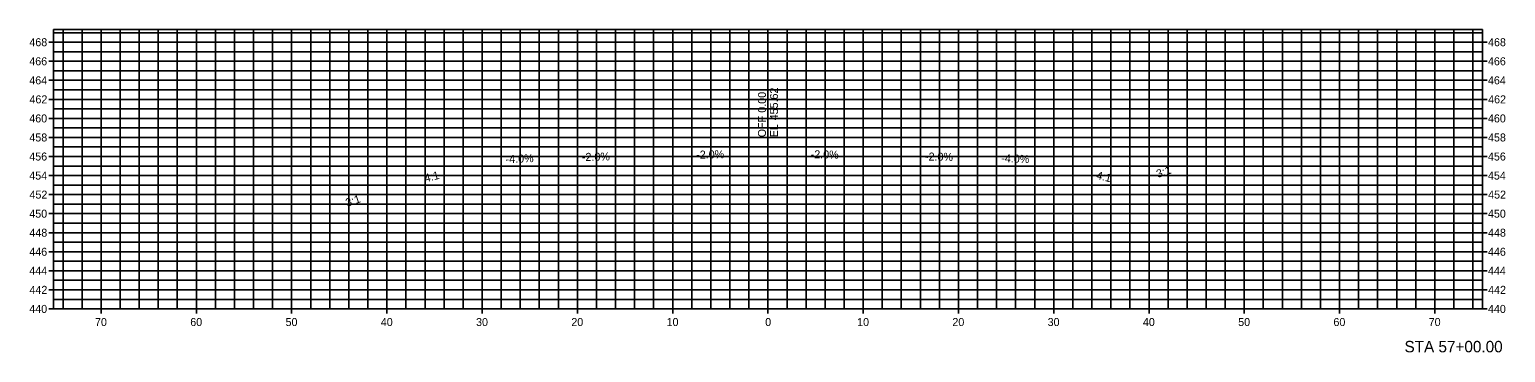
# Model space of a CAD drawing. Extents: x -78 to 77, y 435 to 469.
import ezdxf

# ---------------------------------------------------------------- set-up
doc = ezdxf.new("R2010")
doc.units = 0
for name, color, linetype in [('DSN_DRFT_XS Border Grid', 7, 'Continuous'), ('DSN_DRFT_XS Grid Annotations', 7, 'Continuous'), ('DSN_RDWY_XS Annotation', 7, 'Continuous')]:
    doc.layers.add(name, color=color, linetype=linetype)

msp = doc.modelspace()

# ---------------------------------------------------------------- linework, layer by layer
at = {"layer": 'DSN_DRFT_XS Border Grid'}
for p, q in [((-75, 468), (-75.48, 468)), ((-75, 469.34), (75, 469.34)), ((-75, 440), (-75, 469.34)), ((-75, 469), (75, 469)), ((-75, 468), (75, 468)), ((-74, 440), (-74, 469.34)), ((-72, 440), (-72, 469.34)), ((-70, 440), (-70, 469.34)), ((-68, 440), (-68, 469.34)), ((-66, 440), (-66, 469.34)), ((-64, 440), (-64, 469.34)), ((-62, 440), (-62, 469.34)), ((-60, 440), (-60, 469.34)), ((-58, 440), (-58, 469.34)), ((-56, 440), (-56, 469.34)), ((-54, 440), (-54, 469.34)), ((-52, 440), (-52, 469.34)), ((-50, 440), (-50, 469.34)), ((-48, 440), (-48, 469.34)), ((-46, 440), (-46, 469.34)), ((-44, 440), (-44, 469.34)), ((-42, 440), (-42, 469.34)), ((-40, 440), (-40, 469.34)), ((-38, 440), (-38, 469.34)), ((-36, 440), (-36, 469.34)), ((-34, 440), (-34, 469.34)), ((-32, 440), (-32, 469.34)), ((-30, 440), (-30, 469.34)), ((-28, 440), (-28, 469.34)), ((-26, 440), (-26, 469.34)), ((-24, 440), (-24, 469.34)), ((-22, 440), (-22, 469.34)), ((-20, 440), (-20, 469.34)), ((-18, 440), (-18, 469.34)), ((-16, 440), (-16, 469.34)), ((-14, 440), (-14, 469.34)), ((-12, 440), (-12, 469.34)), ((-10, 440), (-10, 469.34)), ((-8, 440), (-8, 469.34)), ((-6, 440), (-6, 469.34)), ((-4, 440), (-4, 469.34)), ((-2, 440), (-2, 469.34)), ((0, 440), (0, 469.34)), ((2, 440), (2, 469.34)), ((4, 440), (4, 469.34)), ((6, 440), (6, 469.34)), ((8, 440), (8, 469.34)), ((10, 440), (10, 469.34)), ((12, 440), (12, 469.34)), ((14, 440), (14, 469.34)), ((16, 440), (16, 469.34)), ((18, 440), (18, 469.34)), ((20, 440), (20, 469.34)), ((22, 440), (22, 469.34)), ((24, 440), (24, 469.34)), ((26, 440), (26, 469.34)), ((28, 440), (28, 469.34)), ((30, 440), (30, 469.34)), ((32, 440), (32, 469.34)), ((34, 440), (34, 469.34)), ((36, 440), (36, 469.34)), ((38, 440), (38, 469.34)), ((40, 440), (40, 469.34)), ((42, 440), (42, 469.34)), ((44, 440), (44, 469.34)), ((46, 440), (46, 469.34)), ((48, 440), (48, 469.34)), ((50, 440), (50, 469.34)), ((52, 440), (52, 469.34)), ((54, 440), (54, 469.34)), ((56, 440), (56, 469.34)), ((58, 440), (58, 469.34)), ((60, 440), (60, 469.34)), ((62, 440), (62, 469.34)), ((64, 440), (64, 469.34)), ((66, 440), (66, 469.34)), ((68, 440), (68, 469.34)), ((70, 440), (70, 469.34)), ((72, 440), (72, 469.34)), ((74, 440), (74, 469.34)), ((75, 440), (75, 469.34)), ((75.48, 468), (75, 468)), ((-75, 467), (75, 467)), ((-75, 466), (-75.48, 466)), ((-75, 466), (75, 466)), ((-75, 465), (75, 465)), ((75.48, 466), (75, 466)), ((-75, 464), (-75.48, 464)), ((-75, 464), (75, 464)), ((75.48, 464), (75, 464)), ((-75, 462), (-75.48, 462)), ((-75, 463), (75, 463)), ((-75, 462), (75, 462)), ((75.48, 462), (75, 462)), ((-75, 461), (75, 461)), ((-75, 460), (-75.48, 460)), ((-75, 460), (75, 460)), ((-75, 459), (75, 459)), ((75.48, 460), (75, 460)), ((-75, 458), (-75.48, 458)), ((-75, 458), (75, 458)), ((75.48, 458), (75, 458)), ((-75, 456), (-75.48, 456)), ((-75, 457), (75, 457)), ((-75, 456), (75, 456)), ((75.48, 456), (75, 456)), ((-75, 454), (-75.48, 454)), ((-75, 455), (75, 455)), ((-75, 454), (75, 454)), ((75.48, 454), (75, 454)), ((-75, 453), (75, 453)), ((-75, 452), (-75.48, 452)), ((-75, 452), (75, 452)), ((-75, 451), (75, 451)), ((75.48, 452), (75, 452)), ((-75, 450), (-75.48, 450)), ((-75, 450), (75, 450)), ((75.48, 450), (75, 450)), ((-75, 448), (-75.48, 448)), ((-75, 449), (75, 449)), ((-75, 448), (75, 448)), ((75.48, 448), (75, 448)), ((-75, 447), (75, 447)), ((-75, 446), (-75.48, 446)), ((-75, 446), (75, 446)), ((-75, 445), (75, 445)), ((75.48, 446), (75, 446)), ((-75, 444), (-75.48, 444)), ((-75, 444), (75, 444)), ((75.48, 444), (75, 444)), ((-75, 442), (-75.48, 442)), ((-75, 443), (75, 443)), ((-75, 442), (75, 442)), ((75.48, 442), (75, 442)), ((-75, 441), (75, 441)), ((-75, 440), (-75.48, 440)), ((-75, 440), (75, 440)), ((-70, 440), (-70, 439.52)), ((-60, 440), (-60, 439.52)), ((-50, 440), (-50, 439.52)), ((-40, 440), (-40, 439.52)), ((-30, 440), (-30, 439.52)), ((-20, 440), (-20, 439.52)), ((-10, 440), (-10, 439.52)), ((0, 440), (0, 439.52)), ((10, 440), (10, 439.52)), ((20, 440), (20, 439.52)), ((30, 440), (30, 439.52)), ((40, 440), (40, 439.52)), ((50, 440), (50, 439.52)), ((60, 440), (60, 439.52)), ((70, 440), (70, 439.52)), ((75.48, 440), (75, 440))]:
    msp.add_line(p, q, dxfattribs=at)
at = {"layer": 'DSN_RDWY_XS Annotation'}
msp.add_line((0, 456.34), (0, 464.02), dxfattribs=at)

# ---------------------------------------------------------------- texts
at = {"layer": 'DSN_DRFT_XS Grid Annotations'}
for s, height, p in [('468', 0.84, (-77.53, 467.58)), ('468', 0.84, (75.59, 467.58)), ('466', 0.84, (-77.54, 465.58)), ('466', 0.84, (75.58, 465.58)), ('464', 0.84, (-77.54, 463.58)), ('464', 0.84, (75.58, 463.58)), ('462', 0.84, (-77.52, 461.58)), ('462', 0.84, (75.6, 461.58)), ('460', 0.84, (-77.54, 459.58)), ('460', 0.84, (75.58, 459.58)), ('458', 0.84, (-77.53, 457.58)), ('458', 0.84, (75.59, 457.58)), ('456', 0.84, (-77.54, 455.58)), ('456', 0.84, (75.58, 455.58)), ('454', 0.84, (-77.54, 453.58)), ('454', 0.84, (75.58, 453.58)), ('452', 0.84, (-77.52, 451.58)), ('452', 0.84, (75.6, 451.58)), ('450', 0.84, (-77.54, 449.58)), ('450', 0.84, (75.58, 449.58)), ('448', 0.84, (-77.53, 447.58)), ('448', 0.84, (75.59, 447.58)), ('446', 0.84, (-77.54, 445.58)), ('446', 0.84, (75.58, 445.58)), ('444', 0.84, (-77.54, 443.58)), ('444', 0.84, (75.58, 443.58)), ('442', 0.84, (-77.52, 441.58)), ('442', 0.84, (75.6, 441.58)), ('440', 0.84, (-77.54, 439.58)), ('440', 0.84, (75.58, 439.58)), ('70', 0.84, (-70.64, 438.2)), ('60', 0.84, (-60.64, 438.2)), ('50', 0.84, (-50.64, 438.2)), ('40', 0.84, (-40.64, 438.2)), ('30', 0.84, (-30.64, 438.2)), ('20', 0.84, (-20.64, 438.2)), ('10', 0.84, (-10.64, 438.2)), ('0', 0.84, (-0.29, 438.2)), ('10', 0.84, (9.36, 438.2)), ('20', 0.84, (19.36, 438.2)), ('30', 0.84, (29.36, 438.2)), ('40', 0.84, (39.36, 438.2)), ('50', 0.84, (49.36, 438.2)), ('60', 0.84, (59.36, 438.2)), ('70', 0.84, (69.36, 438.2)), ('STA 57+00.00', 1.2, (66.82, 435.44))]:
    msp.add_text(s, height=height, dxfattribs=at).set_placement(p)
at = {"layer": 'DSN_RDWY_XS Annotation'}
for s, rotation, p in [('0.00', 90, (-0.21, 460.6)), ('455.62', 90, (1.05, 459.8)), ('OFF ', 90, (-0.21, 458.02)), ('EL ', 90, (1.05, 458.02)), ('-4.0%', 2.2906, (-27.52, 455.3)), ('-2.0%', 1.1458, (-19.52, 455.53)), ('-2.0%', 1.1458, (-7.52, 455.77)), ('-2.0%', 358.8542, (4.48, 455.83)), ('-2.0%', 358.8542, (16.48, 455.59)), ('-4.0%', 357.7094, (24.48, 455.42)), ('4:1', 14.0362, (-35.95, 453.29)), ('4:1', 345.9638, (34.41, 453.67)), ('3:1', 18.4349, (40.93, 453.75)), ('3:1', 18.4349, (-44.17, 450.72))]:
    msp.add_text(s, height=0.84, rotation=rotation, dxfattribs=at).set_placement(p)

doc.saveas('drawing.dxf')
